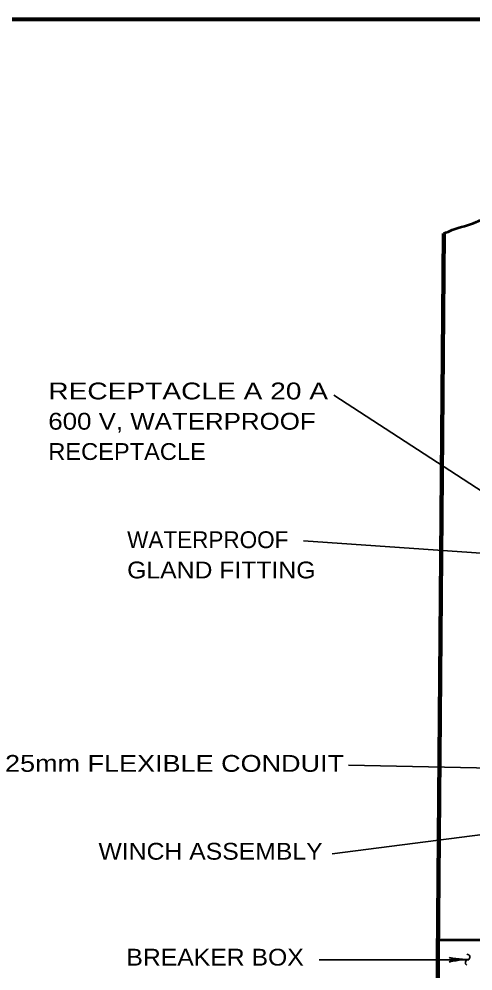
# Model space of a CAD drawing. Extents: x -24 to 689, y -7 to 446.
# Drawn here: x 332.4 to 399.8, y 299.1 to 440.6 of the extents above; entities that cross this region are included whole.
import ezdxf
from ezdxf.enums import TextEntityAlignment as Align

# ---------------------------------------------------------------- set-up
doc = ezdxf.new("R2010")
doc.units = 0
doc.layers.add('1', color=7, linetype='Continuous', lineweight=35)

msp = doc.modelspace()

# ---------------------------------------------------------------- linework, layer by layer
at = {"layer": '1', "lineweight": 106}
msp.add_line((394.317, 267.245), (395.488, 408.744), dxfattribs=at)
at = {"layer": '1'}
for p, q in [((409.753, 364.833), (379.138, 384.739)), ((403.988, 361.012), (374.655, 363.083)), ((402.738, 329.286), (381.329, 329.733)), ((408.113, 320.317), (378.919, 316.544)), ((399.147, 300.794), (376.951, 300.794))]:
    msp.add_line(p, q, dxfattribs=at)
at = {"layer": '1', "lineweight": 53}
msp.add_line((394.619, 303.745), (402.738, 303.745), dxfattribs=at)
at = {"layer": '1', "lineweight": 158}
msp.add_lwpolyline([(683.413, 440.647), (23.663, 440.564), (23.747, 2.23)], dxfattribs=at)
at = {"layer": '1'}
for centre, start, end in [((398.93, 301.176), 299.62508, 90.22616), ((399.145, 300.355), 89.77384, 240.37492)]:
    msp.add_arc(centre, 0.439, start, end, dxfattribs=at)
at = {"layer": '1', "lineweight": 40}
for centre, major_axis, ratio, start_param, end_param in [((398.056, 300.518), (1.786, 0.156), 0.122415, 0.8963533, 3.1415927), ((398.056, 300.518), (1.786, 0.156), 0.122415, 0.8963533, 3.1415927), ((398.026, 301.006), (1.756, -0.176), 0.07063, 3.1407148, 5.41811), ((398.026, 301.006), (1.756, -0.176), 0.07063, 3.1407148, 5.41811)]:
    msp.add_ellipse(centre, major_axis=major_axis, ratio=ratio, start_param=start_param, end_param=end_param, dxfattribs=at)
at = {"layer": '1', "lineweight": 53}
msp.add_spline([(395.488, 408.744), (396.751, 409.29), (400.362, 410.494), (402.168, 411.216), (405.177, 410.855), (409.029, 410.975), (411.437, 411.818), (413.483, 412.661), (417.456, 413.865), (421.548, 413.865), (424.799, 413.745), (427.086, 412.42), (430.697, 410.373), (433.827, 409.049), (436.596, 408.688), (439.966, 407.965), (442.494, 408.326), (445.022, 408.085), (449.488, 408.744)], degree=3, dxfattribs=at)

# ---------------------------------------------------------------- texts
at = {"layer": '1'}
for s, width, p in [('RECEPTACLE A 20 A', 1.25, (336.716, 384.096)), ('600 V, WATERPROOF', 1.15, (336.716, 379.596)), ('RECEPTACLE', 1.05, (336.716, 375.096)), ('GLAND FITTING', 1.1, (348.437, 357.486))]:
    msp.add_text(s, height=2.5, dxfattribs=dict(at, width=width)).set_placement(p)
msp.add_text('WATERPROOF', height=2.5, dxfattribs=at).set_placement((348.437, 361.986))
for s, width, p in [('25mm FLEXIBLE CONDUIT', 1.2, (355.48, 328.73)), ('WINCH ASSEMBLY', 1.1, (360.829, 315.664)), ('BREAKER BOX', 1.1, (361.499, 299.919))]:
    msp.add_text(s, height=2.5, dxfattribs=dict(at, width=width)).set_placement(p, align=Align.CENTER)

doc.saveas('drawing.dxf')
